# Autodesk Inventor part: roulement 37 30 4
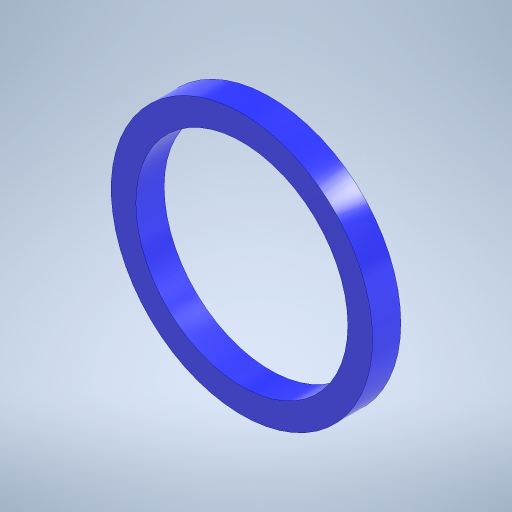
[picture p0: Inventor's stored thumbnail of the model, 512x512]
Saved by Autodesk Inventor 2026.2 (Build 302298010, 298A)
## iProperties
Created: 2025-06
Part Number: roulement 37 30 4
Material: Acier
Document SubType Name: Modeling
Designer: mel
Density: 7.85 g/cm^3
Appearance: Bleu - Peinture murale - Brillant
Author: mel
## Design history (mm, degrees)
sketch "Esquisse1"
  geometry: C1 r 15 at (0, 0); C2 r 18.5 at (0, 0); 1 further point
  constraints: 2 centre point, 2 coincident
  dimensions: "d0" = 30 diameter of C1; "d1" = 37 diameter of C2
extrude "Extrusion1" new body sketch "Esquisse1" distance "d2" = 4; taper "d3" = 0 deg
node "Solide1"
